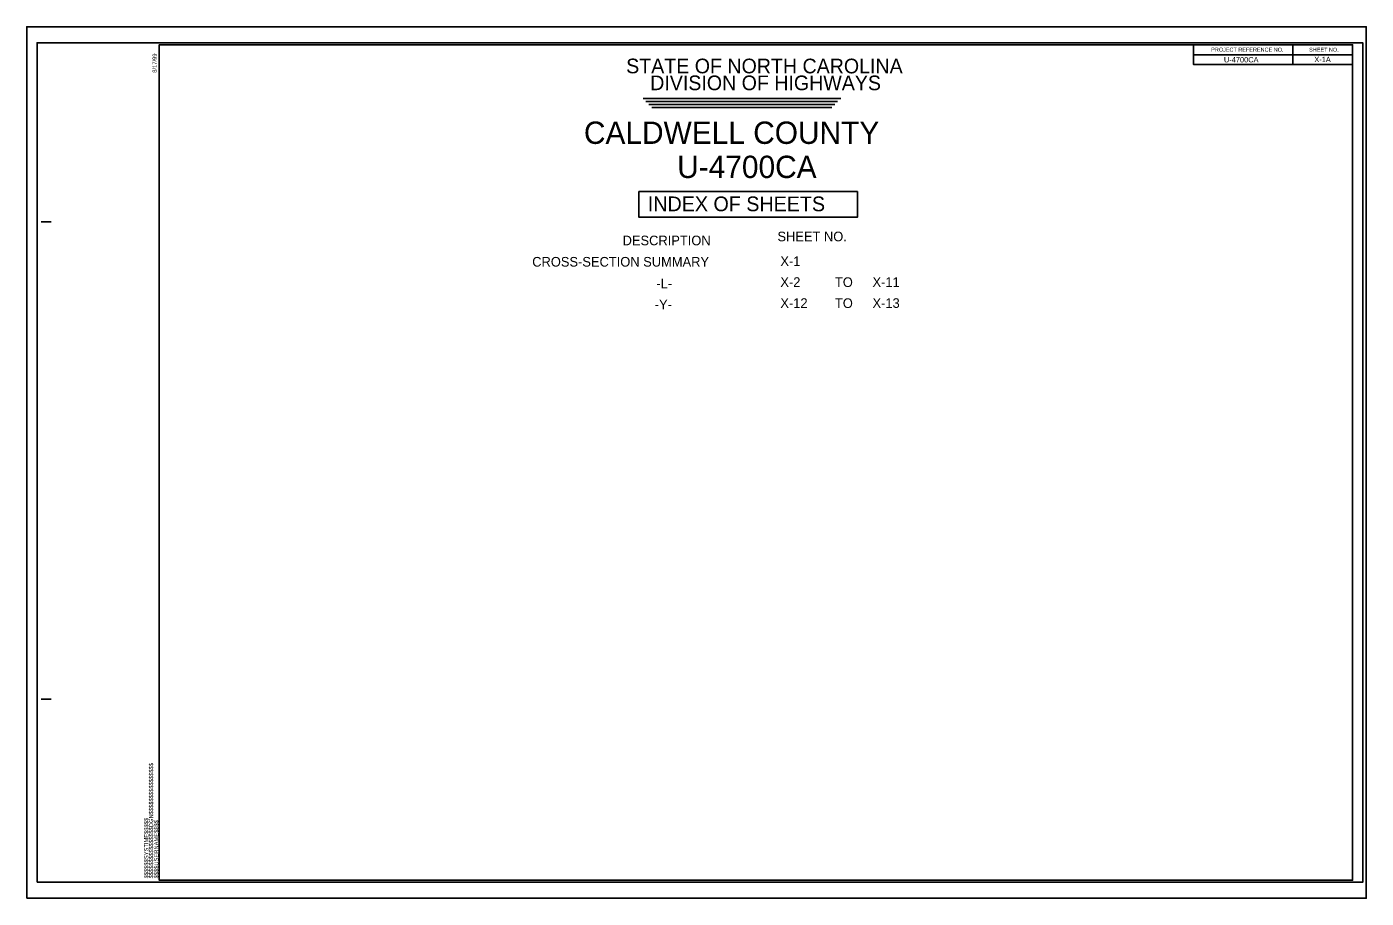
# Model space of a CAD drawing. Extents: x 2021 to 2189, y -3375 to -3266.
import ezdxf

# ---------------------------------------------------------------- set-up
doc = ezdxf.new("R2010")
doc.units = 0
for name, color, linetype in [('Default', 7, 'Continuous'), ('Old_Level_12', 7, 'Continuous'), ('Old_Level_40', 7, 'Continuous'), ('Old_Level_44', 7, 'Continuous'), ('Sheet Block Title CELL', 7, 'Continuous'), ('Sheet Data Field CELL', 7, 'Continuous'), ('Sheet Plan CELL', 7, 'Continuous'), ('Sheet Plot Border Inside CELL', 7, 'Continuous'), ('Sheet Plot Border Outside CELL', 7, 'Continuous')]:
    doc.layers.add(name, color=color, linetype=linetype)

msp = doc.modelspace()

# ---------------------------------------------------------------- linework, layer by layer
at = {"layer": 'Default'}
msp.add_lwpolyline([(2098.08, -3286.3), (2125.55, -3286.3), (2125.55, -3289.51), (2098.08, -3289.51)], close=True, dxfattribs=at)
at = {"layer": 'Old_Level_12'}
for p, q in [((2098.61, -3274.59), (2123.45, -3274.59)), ((2098.61, -3274.59), (2123.45, -3274.59)), ((2098.96, -3274.98), (2123.06, -3274.98)), ((2099.34, -3275.34), (2122.7, -3275.34)), ((2099.71, -3275.71), (2122.31, -3275.71))]:
    msp.add_line(p, q, dxfattribs=at)
at = {"layer": 'Sheet Block Title CELL'}
for p, q in [((2167.79, -3269.09), (2187.79, -3269.09)), ((2180.29, -3267.84), (2180.29, -3270.34)), ((2167.79, -3270.34), (2187.79, -3270.34))]:
    msp.add_line(p, q, dxfattribs=at)
msp.add_lwpolyline([(2167.79, -3267.84), (2187.79, -3267.84), (2187.79, -3270.34), (2167.79, -3270.34)], close=True, dxfattribs=at)
at = {"layer": 'Sheet Plan CELL'}
for p, q in [((2037.79, -3267.84), (2037.79, -3267.84)), ((2022.94, -3290.09), (2024.19, -3290.09)), ((2022.94, -3350.09), (2024.19, -3350.09)), ((2037.79, -3372.84), (2037.79, -3372.84))]:
    msp.add_line(p, q, dxfattribs=at)
msp.add_lwpolyline([(2187.79, -3267.84), (2037.79, -3267.84), (2037.79, -3372.84), (2187.79, -3372.84)], close=True, dxfattribs=at)
at = {"layer": 'Sheet Plot Border Inside CELL'}
msp.add_lwpolyline([(2022.44, -3373.09), (2189.05, -3373.09), (2189.05, -3267.59), (2022.44, -3267.59)], close=True, dxfattribs=at)
at = {"layer": 'Sheet Plot Border Outside CELL'}
msp.add_lwpolyline([(2021.14, -3375.09), (2189.5, -3375.09), (2189.5, -3265.59), (2021.14, -3265.59)], close=True, dxfattribs=at)

# ---------------------------------------------------------------- texts
at = {"layer": 'Default'}
for s, height, p in [('INDEX OF SHEETS', 1.8509, (2099.2, -3288.76)), ('DESCRIPTION', 1.2112, (2096.03, -3293.04)), ('SHEET NO.', 1.211, (2115.49, -3292.54))]:
    msp.add_text(s, height=height, rotation=359.992, dxfattribs=at).set_placement(p)
for s, height, p in [('CROSS-SECTION SUMMARY', 1.2112, (2084.67, -3295.72)), ('X-1', 1.211, (2115.86, -3295.64)), ('-L-', 1.211, (2100.27, -3298.44)), ('X-2', 1.211, (2115.86, -3298.27)), ('TO', 1.211, (2122.72, -3298.28)), ('X-11', 1.211, (2127.44, -3298.27)), ('X-12', 1.211, (2115.86, -3300.91)), ('TO', 1.211, (2122.72, -3300.92)), ('X-13', 1.211, (2127.44, -3300.91)), ('-Y-', 1.211, (2100.07, -3301.08))]:
    msp.add_text(s, height=height, dxfattribs=at).set_placement(p)
at = {"layer": 'Old_Level_40'}
for s, height, p in [('CALDWELL COUNTY', 2.8069, (2091.17, -3280.3)), ('U-4700CA', 2.807, (2102.89, -3284.59))]:
    msp.add_text(s, height=height, rotation=359.9982, dxfattribs=at).set_placement(p)
at = {"layer": 'Old_Level_44'}
for s, p in [('STATE OF NORTH CAROLINA', (2096.48, -3271.43)), ('DIVISION OF HIGHWAYS', (2099.5, -3273.55))]:
    msp.add_text(s, height=1.8416, rotation=359.9915, dxfattribs=at).set_placement(p)
at = {"layer": 'Sheet Block Title CELL'}
for s, p in [('PROJECT REFERENCE NO.', (2170.01, -3268.71)), ('SHEET NO.', (2182.32, -3268.72))]:
    msp.add_text(s, height=0.5, dxfattribs=at).set_placement(p)
at = {"layer": 'Sheet Data Field CELL'}
for s, p in [('U-4700CA', (2171.61, -3270.06)), ('X-1A', (2182.97, -3270.03))]:
    msp.add_text(s, height=0.675, dxfattribs=at).set_placement(p)
at = {"layer": 'Sheet Plan CELL'}
for s, p in [('8/17/99', (2037.47, -3271.36)), ('$$$$$$$$$$$$$$$$DGN$$$$$$$$$$$$$$$$', (2037.03, -3372.6)), ('$$$$$$SYSTIME$$$$$', (2036.42, -3372.6)), ('$$$$USERNAME$$$$', (2037.68, -3372.6))]:
    msp.add_text(s, height=0.525, rotation=90, dxfattribs=at).set_placement(p)

doc.saveas('drawing.dxf')
